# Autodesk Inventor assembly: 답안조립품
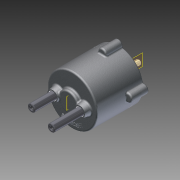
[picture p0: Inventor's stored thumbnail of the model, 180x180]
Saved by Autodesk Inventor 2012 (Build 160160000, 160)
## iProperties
Created: 2015-02
Part Number: 답안조립품
Document SubType Name: Assembly
Designer: Owner
Mass: 1967.32 g
Surface Area: 1692.79 cm^2
Volume: 412.89 cm^3
Density: 4.76475 g/cm^3
Author: Owner
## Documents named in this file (13)
- C:\Documents and Settings\Owner\바탕 화면\350207V1004\답안조립품.iam
- C:\Documents and Settings\Owner\바탕 화면\350207V1004\몸체.ipt
- C:\Documents and Settings\Owner\바탕 화면\350207V1004\메인 축.ipt
- C:\Documents and Settings\Owner\바탕 화면\350207V1004\커버.ipt
- C:\Documents and Settings\Owner\바탕 화면\350207V1004\판캠.ipt
- C:\Documents and Settings\Owner\바탕 화면\350207V1004\슬라이드 축.ipt
- C:\Documents and Settings\Owner\바탕 화면\350207V1004\베어링 NA 4900.ipt
- C:\Documents and Settings\Owner\바탕 화면\350207V1004\오일실.ipt
- C:\Documents and Settings\Owner\바탕 화면\350207V1004\멈춤링 10 x 1.ipt
- C:\Documents and Settings\Owner\바탕 화면\350207V1004\멈춤링 22 x 1.2.ipt
- C:\Documents and Settings\Owner\바탕 화면\350207V1004\M5x0.5x20.ipt
- C:\Documents and Settings\Owner\바탕 화면\350207V1004\가변스프링1.ipt
- C:\Documents and Settings\Owner\바탕 화면\350207V1004\가변스프링2.ipt
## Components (6 placed, 3 different names)
1. 가변스프링1:1
2. 가변스프링2:1
3. M5x0.5x20:1 — 각도:1
4. M5x0.5x20:2
5. M5x0.5x20:3
6. M5x0.5x20:4
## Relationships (1: Angle 1)
- 각도:1 [Angle]: M5x0.5x20:1
